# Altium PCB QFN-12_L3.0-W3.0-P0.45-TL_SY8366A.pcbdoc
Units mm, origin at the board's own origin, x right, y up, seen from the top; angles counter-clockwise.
Board outline 15.9 x 16.32 mm, 2 copper layers (Top Layer, Bottom Layer), stack 0 mm thick; 1 components, 0 nets, 12 pads, 0 vias.
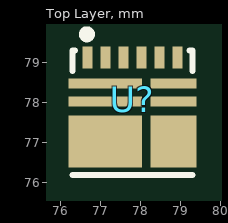
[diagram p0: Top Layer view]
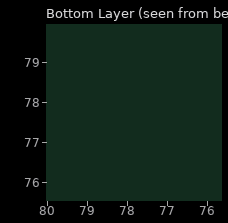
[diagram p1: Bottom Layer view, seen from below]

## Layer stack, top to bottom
Top Layer: signal copper (thickness not stored)
Bottom Layer: signal copper (thickness not stored)

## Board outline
85.75,69.85 69.85,69.85 69.85,86.165 85.75,86.165

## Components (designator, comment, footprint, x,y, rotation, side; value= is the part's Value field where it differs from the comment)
U? "" QFN-12_L3.0-W3.0-P0.45-TL_SY8366A 77.8,78.09 r0 top

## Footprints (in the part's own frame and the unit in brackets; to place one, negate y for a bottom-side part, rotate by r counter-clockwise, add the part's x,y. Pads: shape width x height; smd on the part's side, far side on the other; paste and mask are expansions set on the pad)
QFN-12_L3.0-W3.0-P0.45-TL_SY8366A [mm]
  rect 0.25x0.55 smd: 1(-1.125,1.05) 2(-0.675,1.05) 3(-0.225,1.05) 4(0.225,1.05) 5(0.675,1.05) 6(1.125,1.05)
  rect 1.15x0.25 smd: 7(1.025,0.4) 8(1.025,-0.05)
  rect 1.15x1.3 smd: 9(1.025,-1.05)
  rect 1.84x1.3 smd: 10(-0.68,-1.05)
  rect 1.84x0.25 smd: 11(-0.68,-0.05) 12(-0.68,0.4)
  silkscreen extent -1.5,-1.89 1.5,1.73

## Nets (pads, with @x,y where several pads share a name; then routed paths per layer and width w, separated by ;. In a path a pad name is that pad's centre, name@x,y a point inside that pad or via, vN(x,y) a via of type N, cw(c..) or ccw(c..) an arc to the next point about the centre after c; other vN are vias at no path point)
pads on no net: U?.1 U?.2 U?.3 U?.4 U?.5 U?.6 U?.7 U?.8 U?.9 U?.10 U?.11 U?.12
